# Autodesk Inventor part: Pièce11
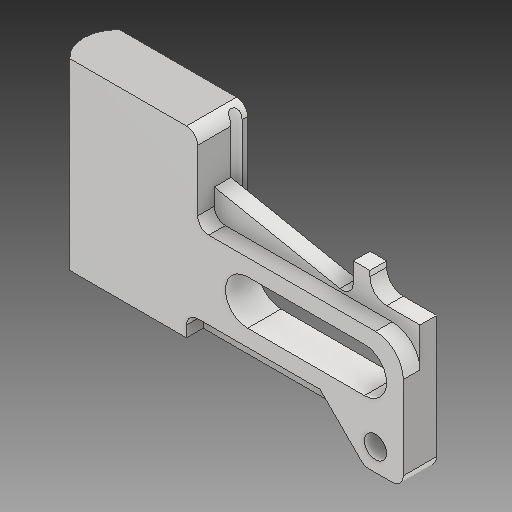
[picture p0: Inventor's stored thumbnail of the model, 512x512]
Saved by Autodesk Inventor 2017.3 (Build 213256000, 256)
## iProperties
Created: 2007-11
Part Number: Pièce11
Material: Générique
Document SubType Name: Modeling
Designer: ficho
Density: 1 g/cm^3
Appearance: Par défaut
Author: ficho
Sending System: SolidWorks 2009
Last Author: christophe
Last Saved: 2011-02-10
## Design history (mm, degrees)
feature "Enlèv. mat.-Extru.3"
node "Solide1"
